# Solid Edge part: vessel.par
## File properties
Author: Lee
Template: Iso Part.par
Last saved by: Lee
Revision: 165
Application: Solid Edge
Material: Aluminum
Face Style: Steel
Fill Style: ANSI32(Steel)
Virtual Style: Machined steel
Coef. of Thermal Exp: 1.3e-05
Thermal Conductivity: 32.0
Specific Heat: 481.0
Modulus of Elasticity: 199947953000.0
Poisson's Ratio: 0.29
Yield Stress: 262000766.0
Ultimate Stress: 358527364.0
Elongation: 0.0
Density: 7833.000 kg/m^3
Accuracy: 0.990
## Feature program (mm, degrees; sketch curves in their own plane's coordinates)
sketch for "unnamed Protrusion 1" #1 plane through (0, 0, 0) normal (0, 0, 1) x-axis (1, 0, 0)
  circle centre (50, 0) radius 850
sketch for "unnamed Protrusion 1" #2 plane through (0, 0, 0) normal (0, 0, 1) x-axis (1, 0, 0)
  circle centre (50, 0) radius 875.4
extrude "unnamed Protrusion 1" add finite 1171.37 along +normal
sketch for "ExtrudedProtrusion_17" #1 plane through (50, 0, 0) normal (0, 0, -1) x-axis (1, 0, 0)
sketch for "ExtrudedProtrusion_17" #2 plane through (50, 0, 0) normal (0, 0, -1) x-axis (1, 0, 0)
  circle centre (0, 0) radius 850
extrude "ExtrudedProtrusion_17" add finite 50.8 along -normal
sketch for "ExtrudedProtrusion_18" #1 plane through (50, 0, 1171.37) normal (0, 0, 1) x-axis (0, -1, 0)
sketch for "ExtrudedProtrusion_18" #2 plane through (50, 0, 1171.37) normal (0, 0, 1) x-axis (0, -1, 0)
  circle centre (0, 0) radius 926.2
extrude "ExtrudedProtrusion_18" add finite 50.8 along -normal
sketch for "Hole_3" plane through (50, 0, 0) normal (0, 0, -1) x-axis (1, 0, 0)
  hole centre (0, 900.8) bore radius 9.525
hole "Hole_3" diameter 19.05 through
sketch for "unnamed RevolvedCutout 1" #1 plane through (0, 0, 0) normal (0, -1, 0) x-axis (1, 0, 0)
  line (918.3, 0) -> (918.3, 12.7)
  line (918.3, 12.7) -> (932.5, 12.7)
  line (932.5, 12.7) -> (932.5, 0)
  line (918.3, 0) -> (932.5, 0)
sketch for "unnamed RevolvedCutout 1" #2 plane through (0, 0, 0) normal (0, -1, 0) x-axis (1, 0, 0)
  line (932.5, 1171.4611) -> (918.3, 1171.4611)
  line (918.3, 1171.4611) -> (918.3, 1158.7611)
  line (918.3, 1158.7611) -> (932.5, 1158.7611)
  line (932.5, 1158.7611) -> (932.5, 1171.4611)
revolve "unnamed RevolvedCutout 1" cut full turn 360 deg about sketch line (50, 1120.57) -> (50, 50.8)
sketch for "Hole_4" plane through (50, 0, 1171.37) normal (0, 0, 1) x-axis (0, -1, 0)
  hole centre (0, 900.8) bore radius 9.525
hole "Hole_4" diameter 19.05 through
sketch for "Hole_5" plane through (50, 0, 1171.37) normal (0, 0, 1) x-axis (0, -1, 0)
  hole centre (-900.8, 0) bore radius 9.525
hole "Hole_5" diameter 19.05 through
sketch for "Hole_6" plane through (50, 0, 1171.37) normal (0, 0, 1) x-axis (0, -1, 0)
  hole centre (0, -900.8) bore radius 9.525
hole "Hole_6" diameter 19.05 through
fillet "Round_1" radius 12.5
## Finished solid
Body 1: solid body, 26 faces, 34 edges, 0 vertices.
  Faces by surface: cylinder 16, plane 8, torus 2
  Edges by curve: circle 34
Bounding box of the edges (mm; curved faces can reach further): 1852.400 x 1852.400 x 1171.370, from (-876.2, -926.2, 0) to (976.2, 926.2, 1171.37).
Cylindrical faces by radius (mm): R9.525 x8, R850 x1, R868.3 x2, R875.4 x1, R882.5 x2, R926.2 x2
Toroidal faces (ring radius, tube radius in mm): R862.5 r12.5 x2
Planar faces by outward normal: +z 4, -z 4
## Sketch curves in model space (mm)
line (50, 0, 0) -> (50, -926.2, 0)
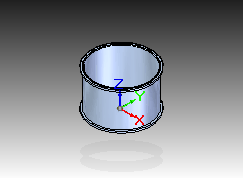
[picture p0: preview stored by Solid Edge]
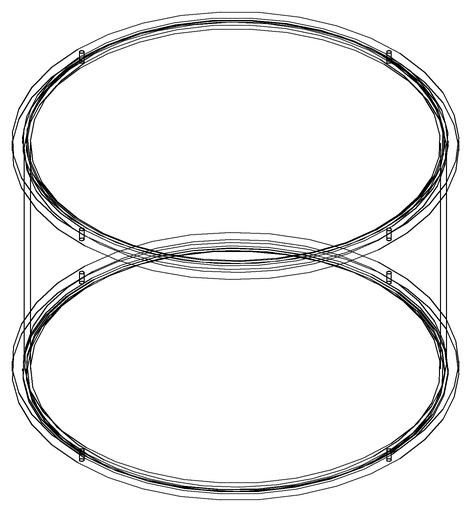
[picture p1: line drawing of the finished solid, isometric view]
